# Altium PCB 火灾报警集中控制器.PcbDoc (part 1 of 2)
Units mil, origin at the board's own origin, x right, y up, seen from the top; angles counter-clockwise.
Board outline 3890 x 3920 mil, 2 copper layers (Top Layer, Bottom Layer); 74 components, 132 nets, 502 pads, 181 vias.
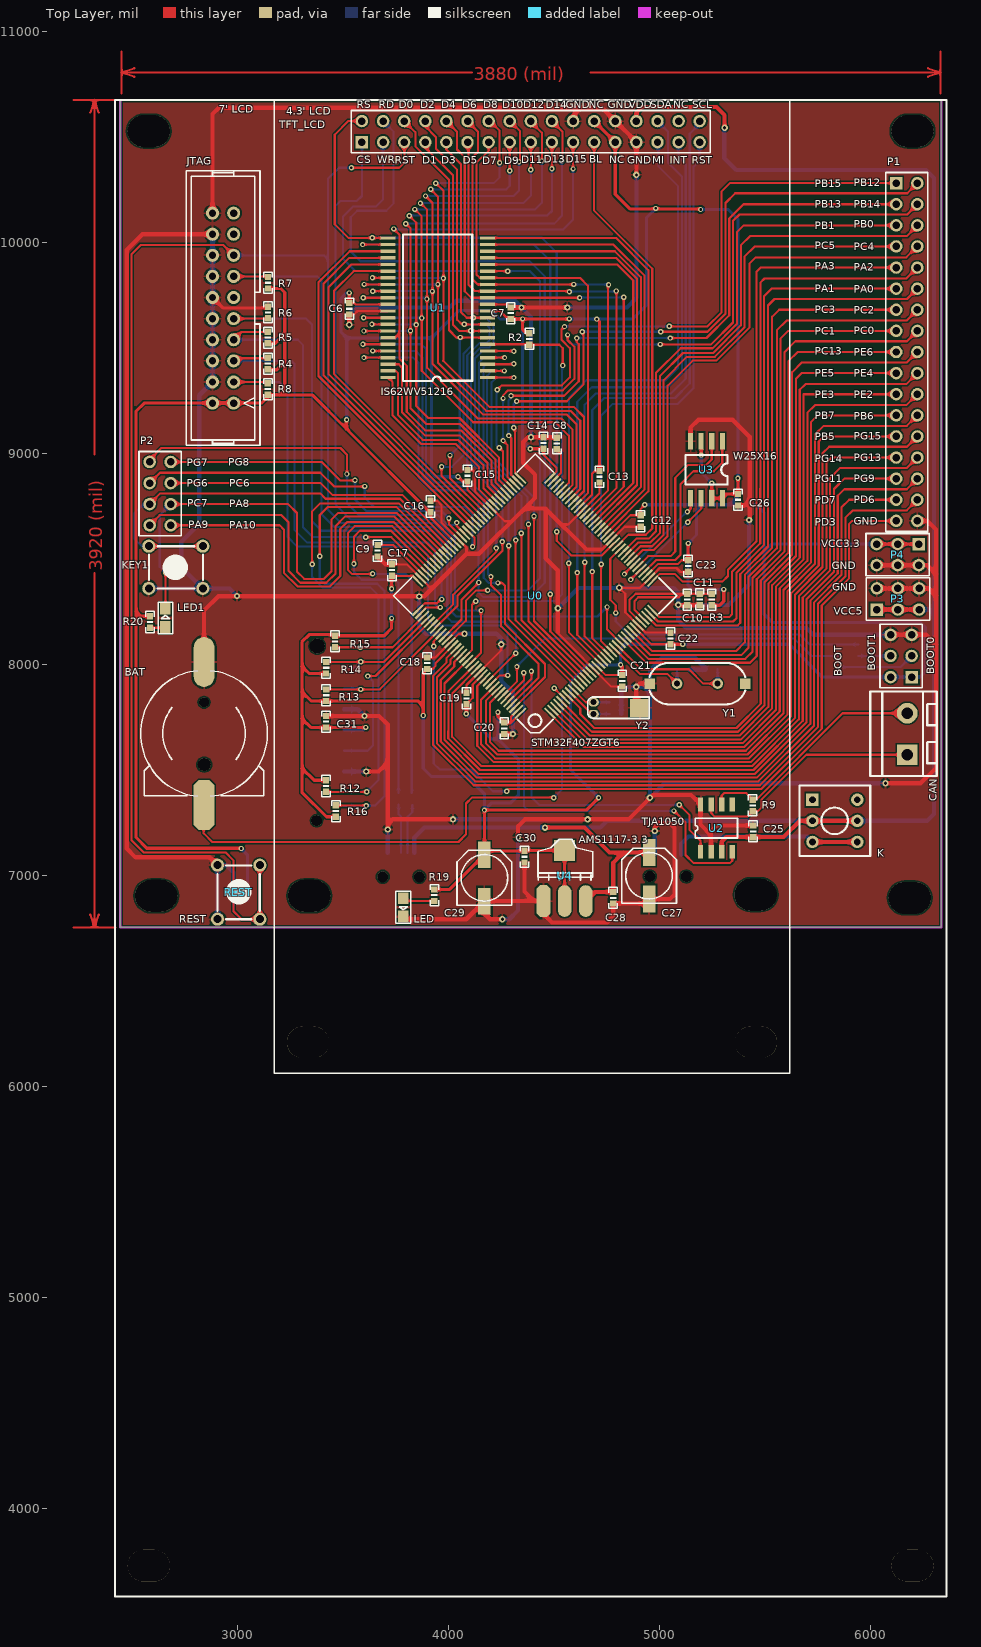
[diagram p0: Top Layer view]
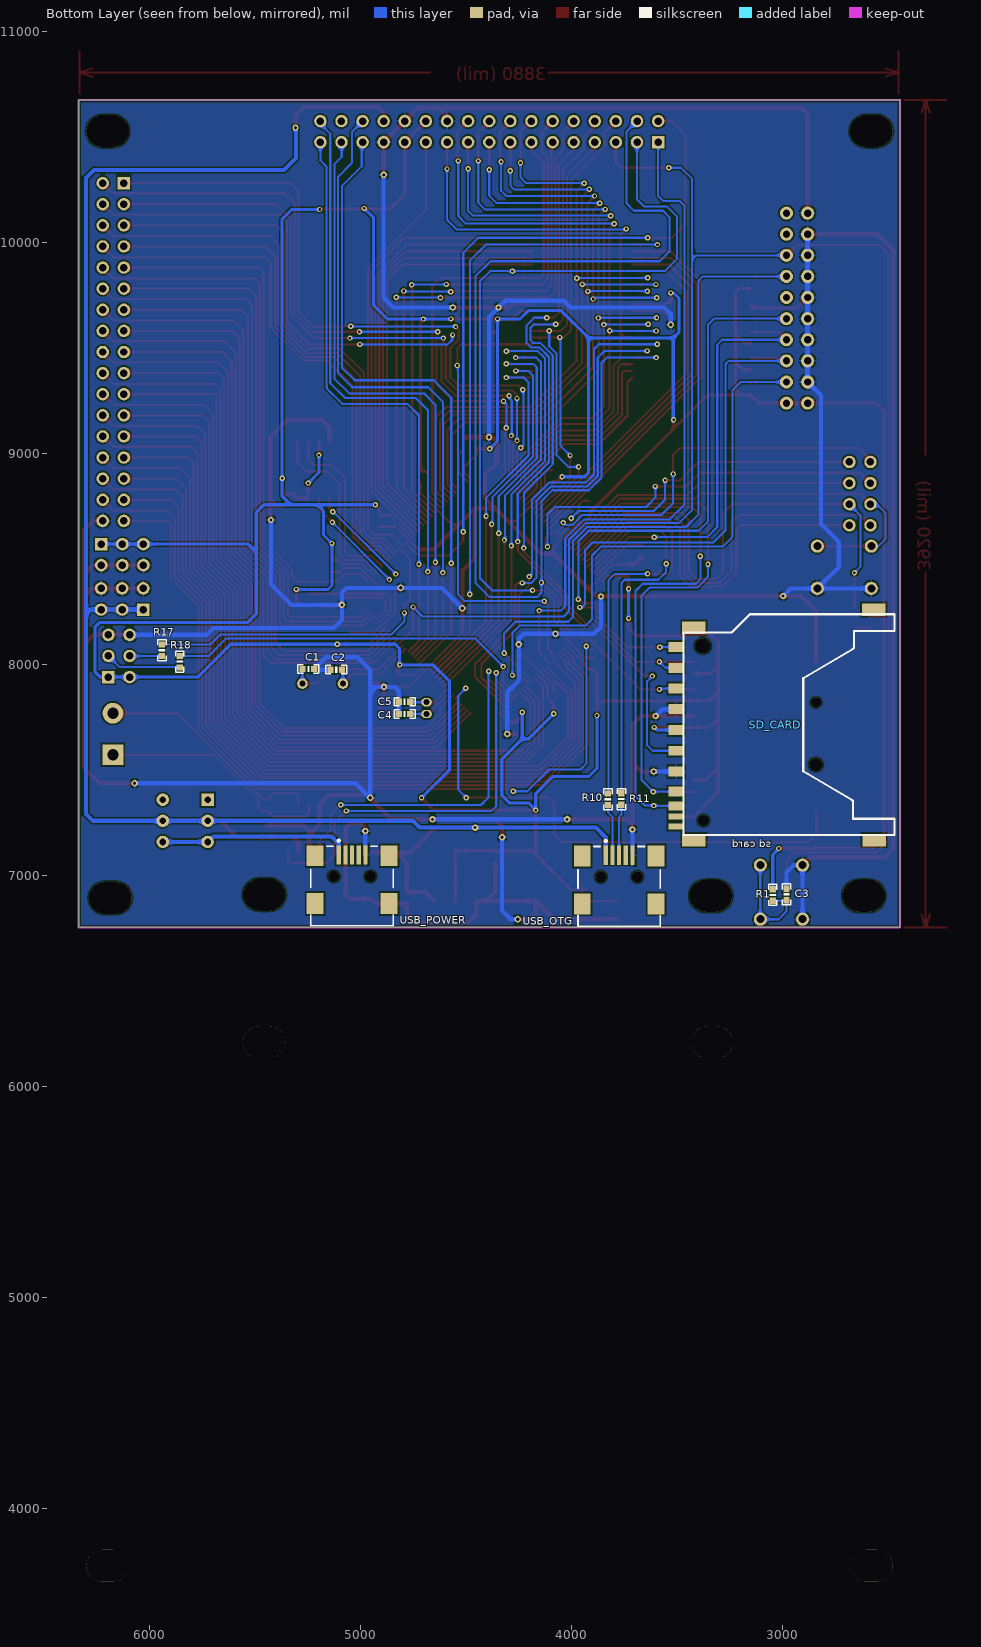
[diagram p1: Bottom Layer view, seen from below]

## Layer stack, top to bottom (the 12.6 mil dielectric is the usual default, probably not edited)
Top Solder: solder mask 0.4, Solder Resist, Dk 3.5
Top Layer: signal copper 1.4
Dielectric 1: dielectric 12.6, FR-4, Dk 4.8
Bottom Layer: signal copper 1.4
Bottom Solder: solder mask 0.4, Solder Resist, Dk 3.5

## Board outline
2445,6755 6335,6755 6335,10675 2445,10675

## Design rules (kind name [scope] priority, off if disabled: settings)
Clearance [All] p1: gap=8
PolygonConnect [All] p1: connectstyle=Relief reliefconductorwidth=10 reliefentries=4 polygonreliefangle="90 Angle" airgapwidth=10
RoutingVias [All] p1: holewidth=28 width=50 viastyle="Through Hole" minholewidth=28 minwidth=50 maxholewidth=28 maxwidth=50
SilkToBoardRegionClearance [InNetClass('All Nets')] p1:
SolderMaskExpansion [All] p1: expansion=4
Width VCC3.3_10mil [InNet('VCC3.3')] p1 off: maxlimit=10 minlimit=10 preferedwidth=10
Width GND_10mil [InNet('GND')] p2 off: maxlimit=10 minlimit=10 preferedwidth=10
Width USB_VCC [InNet('USB_VCC')] p3: maxlimit=20 minlimit=20 preferedwidth=20
Width GND_20mil [InNet('GND')] p4: maxlimit=20 minlimit=20 preferedwidth=20
Width VCC5 [InNet('VCC5')] p5: maxlimit=20 minlimit=20 preferedwidth=20
Width VCC3.3_mil [InNet('VCC3.3')] p6: maxlimit=15 minlimit=15 preferedwidth=15
Width [All] p7: maxlimit=10 minlimit=10 preferedwidth=10
28 further rules are at their usual default settings.

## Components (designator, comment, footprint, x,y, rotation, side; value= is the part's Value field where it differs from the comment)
BAT "BATT" BATM 2842,7674 r0 top (schematic designator BAT1)
BOOT "Header 3X2" HDR2X3 6194,7941 r90 top
C1 "22" 0603P 5247,7979 r0 bottom
C2 "22" 0603P 5115,7976 r180 bottom
C3 "104" 0603P 2982,6912 r270 bottom
C4 "10" 0603P 4791,7766 r0 bottom
C5 "10" 0603P 4791,7824 r0 bottom
C6 "104" 0603P 3530,9686 r90 top
C7 "104" 0603P 4295,9665 r270 top
C8 "225" 0603P 4513,9048 r90 top
C9 "225" 0603P 3664,8540 r270 top
C10 "10uF" 0603P 5131,8308 r90 top
C11 "104" 0603P 5190,8309 r90 top
C12 "104" 0603P 4910,8680 r90 top
C13 "104" 0603P 4715,8890 r90 top
C14 "104" 0603P 4450,9050 r270 top
C15 "104" 0603P 4090,8895 r270 top
C16 "104" 0603P 3915,8749 r270 top
C17 "104" 0603P 3732,8448 r270 top
C18 "104" 0603P 3899,8007 r270 top
C19 "104" 0603P 4085,7840 r270 top
C20 "104" 0603P 4264,7698 r90 top
C21 "104" 0603P 4823,7923 r90 top
C22 "104" 0603P 5052,8124 r270 top
C23 "104" 0603P 5135,8467 r90 top
C25 "104" 0603P 5443,7210 r90 top
C26 "104" 0603P 5371,8781 r90 top
C27 "220uF" CC6.56.5 4950,7000 r270 top
C28 "104" 0603P 4780,6895 r90 top
C29 "220uF" CC6.56.5 4170,6990 r270 top
C30 "104" 0603P 4360,7090 r90 top
C31 "104" 0603P 3420,7730 r270 top
CAN "CAN" HEAD2L-0.8 6173,7573 r90 top (schematic designator CAN1)
JTAG "JTAG" JTAG_20 2932,9689 r90 top (schematic designator JTAG1)
K "BUTTON" BTN8.5*8.5 5724,7360 r0 top (schematic designator K2)
KEY1 "KEY_M" KEY_M 2836,8361 r180 top
LED "LED" SMDLED 3786,6894 r270 top (schematic designator LED1)
LED1 "LED" SMDLED 2659,8178 r90 top (schematic designator LED2)
P1 "Header2x17" Header2x17 6121,10281 r0 top
P2 "Header2x4" Header2x4 2584,8960 r0 top
P3 "VCC5" HDR2X3 6029,8261 r0 top
P4 "VCC3.3" HDR2X3 6228,8571 r180 top
R1 "10K" 0603P 3047,6909 r270 bottom
R2 "10K" 0603P 4383,9543 r270 top
R3 "10R" 0603P 5247,8308 r270 top
R4 "10K" 0603P 3144,9426 r90 top
R5 "10K" 0603P 3144,9549 r90 top
R6 "10K" 0603P 3145,9669 r270 top
R7 "10K" 0603P 3145,9809 r90 top
R8 "10K" 0603P 3144,9305 r90 top
R9 "120R" 0603P 5441,7333 r90 top
R10 "22R" 0603P 3828,7362 r90 bottom
R11 "22R" 0603P 3764,7363 r90 bottom
R12 "47K" 0603P 3420,7425 r270 top
R13 "47K" 0603P 3420,7855 r90 top
R14 "47K" 0603P 3420,7985 r90 top
R15 "47K" 0603P 3462,8110 r270 top
R16 "47K" 0603P 3466,7306 r90 top
R17 "10K" 0603P 5941,8068 r90 bottom
R18 "10K" 0603P 5856,8014 r270 bottom
R19 "200R" 0603P 3933,6908 r270 top
R20 "200R" 0603P 2586,8202 r270 top
REST "REST" KEY_M 2906,6794 r90 top
SD_CARD "sd card" SDCARD_L 3505,7985 r90 bottom
TFT_LCD "ATK 7‘ TFT LCD" "7’ TFT LCD" 3590,10475 r0 top locked (schematic designator TFT_LCD1)
U0 "STM32F407ZGT6" LQFP144 4480,7770 r135 top
U1 "IS62WV51216" TSOP44 4185,9360 r180 top
U2 "TJA1050" SOP-8 5194,7113 r90 top
U3 "W25X16" SOIC-8 5297,9058 r270 top
U4 "AMS1117-3.3" AMS1117 4450,6880 r0 top
USB_OTG "USB-B(Mini)" USB/SM0.8-6H5 3775,6788 r270 bottom
USB_POWER "USB-B(Mini)" USB/SM0.8-6H5 5040,6790 r270 bottom
Y1 "8MHz" XTAL_US 5275,7910 r180 top
Y2 "32.768K" XTAL32 4687,7822 r0 top

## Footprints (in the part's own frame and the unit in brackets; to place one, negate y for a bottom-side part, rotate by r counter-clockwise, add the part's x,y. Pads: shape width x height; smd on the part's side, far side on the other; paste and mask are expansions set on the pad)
"7’ TFT LCD" [mm]
  rect 1.5x1.5 hole 0.9: 1(0,0)
  round 1.5 hole 0.9: 2(0,2.54) 3(2.54,0) 4(2.54,2.54) 5(5.08,0) 6(5.08,2.54) 7(7.62,0) 8(7.62,2.54) 9(10.16,0) 10(10.16,2.54) 11(12.7,0) 12(12.7,2.54) 13(15.24,0) 14(15.24,2.54) 15(17.78,0) 16(17.78,2.54) 17(20.32,0) 18(20.32,2.54) 19(22.86,0) 20(22.86,2.54) 21(25.4,0) 22(25.4,2.54) 23(27.94,0) 24(27.94,2.54) 25(30.48,0) 26(30.48,2.54) 27(33.02,0) 28(33.02,2.54) 29(35.56,0) 30(35.56,2.54) 31(38.1,0) 32(38.1,2.54) 33(40.64,0) 34(40.64,2.54)
  oval 5.08x3.81 hole 3.81 slot 5.08 at 0 deg unplated: ""(-25.654,-171.272) ""(-25.654,1.321) ""(-6.477,-108.306) ""(47.396,-108.306) ""(66.243,-171.272) ""(66.243,1.321)
  silkscreen extent -29.72,-175.01 70.36,5.08
0603P [mil]
  rect 30x30 smd: 1(-27,0) 2(27.5,-0.06)
  silkscreen extent -50,-20 50,20
AMS1117 [mil]
  oct 65x150 smd: 1(0.03,-0.06)
  oval 65x150 smd: 2(100.03,-0.06) 3(200.03,-0.06)
  rect 100x100 smd: 4(100.03,239.94)
  silkscreen extent -26,100 234,293
BATM [mil]
  oct 98.43x236.22 smd: 1(0,-338.65)
  oval 98.43x236.22 smd: 2(0,338.52)
  round 45 hole 45 slot 46 at 0 deg unplated paste+0 mask+0: ""(0,147.57)
  round 60 hole 60 slot 61 at 0 deg unplated paste+0 mask+0: ""(0.98,-147.7)
  silkscreen extent -300,-298 300,298
BTN8.5*8.5 [mm]
  rect 1.5x1.5 hole 0.8: 1(0,0)
  round 1.5 hole 0.8: 2(0,-2.54) 3(0,-5.08) 4(5.4,-5.08) 5(5.4,-2.54) 6(5.4,0)
  silkscreen extent -1.55,-6.79 6.95,1.71
CC6.56.5 [mm]
  rect 3.2x1.5 smd: 1(-2.794,0) 2(2.8,0)
  silkscreen extent -3.3,-3.3 3.3,3.3
HDR2X3 [mm]
  rect 1.5x1.5 hole 0.9: 1(0,0)
  round 1.5 hole 0.9: 2(0,2.54) 3(2.54,0) 4(2.54,2.54) 5(5.08,0) 6(5.08,2.54)
  silkscreen extent -1.27,-1.27 6.35,3.81
HEAD2L-0.8 [mm]
  rect 2.5x2.5 hole 1.35: 1(0,0)
  round 2.5 hole 1.35: 2(5,0)
  silkscreen extent -2.54,-3.56 7.62,4.45
Header2x4 [mm]
  round 1.5 hole 0.9: 1(0,0) 2(2.54,0) 3(0,-2.54) 4(2.54,-2.54) 5(0,-5.08) 6(2.54,-5.08) 7(0,-7.62) 8(2.54,-7.62)
  silkscreen extent -1.27,-8.89 3.81,1.27
Header2x17 [mm]
  rect 1.5x1.5 hole 0.9: 1(0,0)
  round 1.5 hole 0.9: 2(2.54,0) 3(0,-2.54) 4(2.54,-2.54) 5(0,-5.08) 6(2.54,-5.08) 7(0,-7.62) 8(2.54,-7.62) 9(0,-10.16) 10(2.54,-10.16) 11(0,-12.7) 12(2.54,-12.7) 13(0,-15.24) 14(2.54,-15.24) 15(0,-17.78) 16(2.54,-17.78) 17(0,-20.32) 18(2.54,-20.32) 19(0,-22.86) 20(2.54,-22.86) 21(0,-25.4) 22(2.54,-25.4) 23(0,-27.94) 24(2.54,-27.94) 25(0,-30.48) 26(2.54,-30.48) 27(0,-33.02) 28(2.54,-33.02) 29(0,-35.56) 30(2.54,-35.56) 31(0,-38.1) 32(2.54,-38.1) 33(0,-40.64) 34(2.54,-40.64)
  silkscreen extent -1.27,-41.91 3.81,1.27
JTAG_20 [mil]
  round 62 hole 35: 1(-450,-50) 2(-450,50) 3(-350,-50) 4(-350,50) 5(-250,-50) 6(-250,50) 7(-150,-50) 8(-150,50) 9(-50,-50) 10(-50,50) 11(50,-50) 12(50,50) 13(150,-50) 14(150,50) 15(250,-50) 16(250,50) 17(350,-50) 18(350,50) 19(450,-50) 20(450,50)
  silkscreen extent -650,-175 650,175
KEY_M [mil]
  round 62 hole 38: 1(0,0) 1(255.91,0) 2(0,-200) 2(255.91,-200)
  silkscreen extent 0,-200 255,0
LQFP144 [mil]
  rect 70.87x10 smd: 1(-0.36,0.02) 2(-0.35,-19.66) 3(-0.35,-39.35) 4(-0.35,-59.03) 5(-0.35,-78.72) 6(-0.35,-98.4) 7(-0.35,-118.09) 8(-0.35,-137.77) 9(-0.35,-157.46) 10(-0.35,-177.14) 11(-0.35,-196.83) 12(-0.36,-216.51) 13(-0.35,-236.2) 14(-0.35,-255.88) 15(-0.35,-275.57) 16(-0.35,-295.25) 17(-0.35,-314.94) 18(-0.35,-334.62) 19(-0.35,-354.31) 20(-0.35,-373.99) 21(-0.36,-393.68) 22(-0.35,-413.36) 23(-0.35,-433.05) 24(-0.35,-452.73) 25(-0.35,-472.42) 26(-0.35,-492.1) 27(-0.35,-511.79) 28(-0.35,-531.47) 29(-0.35,-551.16) 30(-0.35,-570.84) 31(-0.35,-590.53) 32(-0.36,-610.21) 33(-0.35,-629.9) 34(-0.35,-649.58) 35(-0.35,-669.27) 36(-0.35,-688.95) 73(885.47,-688.95) 74(885.47,-669.27) 75(885.47,-649.58) 76(885.47,-629.9) 77(885.47,-610.21) 78(885.47,-590.53) 79(885.47,-570.84) 80(885.47,-551.16) 81(885.47,-531.47) 82(885.47,-511.79) 83(885.47,-492.1) 84(885.47,-472.42) 85(885.47,-452.73) 86(885.47,-433.05) 87(885.47,-413.36) 88(885.47,-393.68) 89(885.47,-373.99) 90(885.47,-354.31) 91(885.47,-334.62) 92(885.47,-314.94) 93(885.47,-295.25) 94(885.47,-275.57) 95(885.47,-255.88) 96(885.47,-236.2) 97(885.47,-216.51) 98(885.47,-196.83) 99(885.47,-177.14) 100(885.47,-157.46) 101(885.47,-137.77) 102(885.47,-118.09) 103(885.47,-98.4) 104(885.47,-78.72) 105(885.47,-59.03) 106(885.47,-39.35) 107(885.47,-19.66) 108(885.47,0.02)
  rect 10x70.87 smd: 37(98.07,-787.37) 38(117.76,-787.38) 39(137.44,-787.38) 40(157.13,-787.38) 41(176.81,-787.38) 42(196.5,-787.38) 43(216.18,-787.38) 44(235.87,-787.38) 45(255.55,-787.38) 46(275.24,-787.38) 47(294.92,-787.38) 48(314.61,-787.37) 49(334.29,-787.38) 50(353.98,-787.38) 51(373.66,-787.38) 52(393.35,-787.38) 53(413.03,-787.38) 54(432.72,-787.38) 55(452.4,-787.38) 56(472.09,-787.38) 57(491.77,-787.38) 58(511.46,-787.37) 59(531.14,-787.38) 60(550.83,-787.38) 61(570.51,-787.38) 62(590.2,-787.38) 63(609.88,-787.38) 64(629.57,-787.38) 65(649.25,-787.38) 66(668.94,-787.38) 67(688.62,-787.38) 68(708.31,-787.37) 69(727.99,-787.38) 70(747.68,-787.38) 71(767.36,-787.38) 72(787.05,-787.38) 109(787.05,98.45) 110(767.36,98.45) 111(747.68,98.45) 112(727.99,98.45) 113(708.31,98.45) 114(688.62,98.45) 115(668.94,98.45) 116(649.25,98.45) 117(629.57,98.45) 118(609.88,98.45) 119(590.2,98.45) 120(570.51,98.45) 121(550.83,98.45) 122(531.14,98.45) 123(511.46,98.45) 124(491.77,98.45) 125(472.09,98.45) 126(452.4,98.45) 127(432.72,98.45) 128(413.03,98.45) 129(393.35,98.45) 130(373.66,98.45) 131(353.98,98.45) 132(334.29,98.45) 133(314.61,98.45) 134(294.92,98.45) 135(275.24,98.45) 136(255.55,98.45) 137(235.87,98.45) 138(216.18,98.45) 139(196.5,98.45) 140(176.81,98.45) 141(157.13,98.45) 142(137.44,98.45) 143(117.76,98.45) 144(98.07,98.45)
  silkscreen extent -32,-819 917,130
SDCARD_L [mm]
  rect 1.2x1.8 smd: 1(0,0) 2(-2.489,0) 3(-4.983,-0.009) 4(-7.483,-0.009) 5(-9.983,-0.009) 6(-12.483,-0.009) 7(-14.908,-0.009) 9(2.517,-0.009)
  rect 1.1x1.8 smd: 8(-16.612,0)
  rect 0.7x1.8 smd: 10(-17.908,-0.009) 12(-19.101,0)
  rect 1.5x2.8 smd: 11(-20.726,-23.834) 11(-20.726,-2.143) 11(4.826,-2.143) 11(7.01,-23.784)
  silkscreen extent -20.13,-26.3 6.44,-0.9
SMDLED [mm]
  rect 1.4x1.27 smd: 1(0.001,-0.002) 2(2.211,-0.002)
  silkscreen extent -0.8,-0.89 3.01,0.89
SOIC-8 [mil]
  rect 80x24 smd: 1(0,0) 2(0,-50.06) 3(0,-100.06) 4(0,-150.06) 5(270,-150) 6(270,-100) 7(270,-50) 8(270,0)
  silkscreen extent 65,-175 205,25
SOP-8 [mil]
  rect 65x25 smd: 1(0,0) 2(0,-50) 3(0,-100) 4(0,-150) 5(224.41,-150) 6(224.41,-100) 7(224.41,-50) 8(224.41,0)
  silkscreen extent 65,-175 159,25
TSOP44 [mm]
  rect 1.8x0.4 smd: 1(-0.009,0.001) 2(-0.009,-0.799) 3(-0.009,-1.599) 4(-0.009,-2.399) 5(-0.009,-3.199) 6(-0.009,-3.999) 7(-0.009,-4.799) 8(-0.009,-5.599) 9(-0.009,-6.399) 10(-0.009,-7.199) 11(-0.009,-7.999) 12(-0.009,-8.799) 13(-0.009,-9.599) 14(-0.009,-10.399) 15(-0.009,-11.199) 16(-0.009,-11.999) 17(-0.009,-12.799) 18(-0.009,-13.599) 19(-0.009,-14.399) 20(-0.009,-15.199) 21(-0.009,-15.999) 22(-0.009,-16.799) 23(11.991,-16.799) 24(11.991,-15.999) 25(11.991,-15.199) 26(11.991,-14.399) 27(11.991,-13.599) 28(11.991,-12.799) 29(11.991,-11.999) 30(11.991,-11.199) 31(11.991,-10.399) 32(11.991,-9.599) 33(11.991,-8.799) 34(11.991,-7.999) 35(11.991,-7.199) 36(11.991,-6.399) 37(11.991,-5.599) 38(11.991,-4.799) 39(11.991,-3.999) 40(11.991,-3.199) 41(11.991,-2.399) 42(11.991,-1.599) 43(11.991,-0.799) 44(11.991,0.001)
  silkscreen extent 1.83,-17.2 10.16,0.4
USB/SM0.8-6H5 [mm]
  rect 2.3x0.5 smd: 1(-7.85,-1.6) 2(-7.85,-0.8) 3(-7.85,0) 4(-7.85,0.8) 5(-7.85,1.6)
  rect 2.5x2 smd: 6(-7.75,4.45) 7(-1.996,4.45) 8(-7.75,-4.45) 9(-1.996,-4.45)
  round 1.27 hole 1.27 slot 1.295 at 0 deg unplated: MH1(-5.25,2.2) MH2(-5.25,-2.2)
  silkscreen extent -9.67,-4.95 0.7,4.95
XTAL32 [mil]
  oval 50x40 hole 28: 1(0,0) 2(0,-56)
  rect 92.13x86 smd: ""(220,-27)
  silkscreen extent -28,-77 264,25
XTAL_US [mil]
  round 50 hole 28: 1(0,0) 2(192.13,0)
  rect 50x50 smd: ""(-130.32,0) ""(322.44,0)
  silkscreen extent -131,-98 323,98

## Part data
BAT: library part BAT
BOOT: "Header, 3-Pin, Dual row"
C1 C2 C3 C4 C5 C6 C7 C8 C9 C10 C11 C12 C13 C14 C15 C16 C17 C18 C19 C20 C21 C22 C23 C25 C26 C28 C30 C31: library part C
C27 C29: library part CAP
CAN: library part HEAD2
LED LED1: library part LED2, "Typical RED, GREEN, YELLOW, AMBER GaAs LED"
P3 P4: library part "Header 3X2", "Header, 3-Pin, Dual row"
R1 R2 R3 R4 R5 R6 R7 R8 R9 R10 R11 R12 R13 R14 R15 R16 R17 R18 R19 R20: library part R
REST: library part KEY
U0: library part STM32F407ZET6, "STM32F407ZET6"
U2: library part SN65HVD230D
U3: "W25X16;SST25VF016;MX25L1605"
U4: library part AMS1117
USB_OTG USB_POWER: library part USB5
Y1 Y2: library part XTAL, "Crystal Oscillator"

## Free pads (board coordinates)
  oval 200x150 hole 150 slot 200 at 0 deg unplated paste+0: ""(2615,6905) ""(3340,6905) ""(5455,6910)
  round 50 hole 50 slot 51 at 0 deg unplated paste+0 mask+0: ""(3375,7261)
  round 70 hole 70 slot 71 at 0 deg unplated paste+0 mask+0: ""(3378,8088)
  oval 200x150 hole 150 slot 200 at 0 deg unplated: ""(6185,6895)

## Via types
v1: diameter 25, hole 12, Top Layer to Bottom Layer, 154 vias
v2: diameter 30, hole 15, Top Layer to Bottom Layer, 27 vias

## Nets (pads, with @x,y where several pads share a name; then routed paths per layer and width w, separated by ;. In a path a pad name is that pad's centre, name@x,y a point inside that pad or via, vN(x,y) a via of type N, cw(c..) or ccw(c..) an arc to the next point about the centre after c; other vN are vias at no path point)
BOOT0: R18.1 U0.138 | length 1787.2
  Top Layer w10: U0.138@4257.52,7853.25 4324,7919.73 v1(4324,7991)
  Bottom Layer w10: v1(4324,7991) 4457.5,8124.5 5636,8124.5 5719.5,8041 R18.1@5856,8041
BOOT1: R17.2 U0.48 | length 1569.9
  Top Layer w10: v1(4792,8245) 4792,8281 4766,8307 4766,8500.92 U0.48@4814.3,8549.22
  Bottom Layer w10: v1(4792,8245) 4792,8204 4853.5,8142.5 5664,8142.5 5711,8095.5 R17.2@5940.94,8095.5
CAN_RX: U0.139 U2.4 | length 2025.5
  Top Layer w10: U0.139@4271.44,7839.33 4357,7924.89 v1(4357,7962) ; v1(5068,7307) 5123,7252 5123,7098 5160,7061 5334,7061 5344,7071 U2.4@5344,7113
  Bottom Layer w10: v1(4357,7962) 4357,7329 4379,7307 v1(5068,7307)
CAN_TX: U0.140 U2.1 | length 1763.4
  Top Layer w10: U0.140@4285.36,7825.41 4393,7933.05 v1(4393,7969) ; v1(5093,7336) 5141,7288 5141,7218 5194,7165 U2.1@5194,7113
  Bottom Layer w10: v1(4393,7969) 4393,7371 4429,7335 v1@5090.46,7335
FSMC_A0: U0.10 U1.5 | length 2082.6
  Top Layer w10: U1.5@4185.35,9485.96 4309.04,9485.96 v1(4310,9485) ; v1(4285,8563) 4285,8215.52 U0.10@4605.51,7895.01
  Bottom Layer w10: v1@4285,8559 4285,8806.63 4125,8966.63 4125,9450 4160,9485 v1(4310,9485)
FSMC_A1: U0.11 U1.4 | length 1933.4
  Top Layer w10: U1.4@4185.35,9454.46 v1(4265.54,9454.46) ; v1(4318,8590) 4318,8210.35 U0.11@4619.43,7908.93
  Bottom Layer w10: v1(4265.54,9454.46) 4167.46,9454.46 4145,9432 4145,8972.09 4315,8802.09 v1@4315,8585
FSMC_A2: U0.12 U1.3 | length 1960.7
  Top Layer w10: U1.3@4185.35,9422.97 4307.97,9422.97 v1(4310,9425) ; v1(4345,8623) 4345,8211.19 U0.12@4633.35,7922.85
  Bottom Layer w10: v1(4310,9425) 4182,9425 4165,9408 4165,8977.54 4345,8797.54 v1@4345,8619
FSMC_A3: U0.13 U1.2 | length 1796.8
  Top Layer w10: U1.2@4185.35,9391.47 v1(4265,9391.47) ; v1(4379,8665) 4379,8205.03 U0.13@4647.27,7936.77
  Bottom Layer w10: v1(4265,9391.47) 4205.47,9391.47 4183,9369 4183,8985 4375,8793 v1@4375,8662
FSMC_A4: U0.14 U1.1 | length 1816.4
  Top Layer w10: U1.1@4185.35,9359.98 v1(4310,9359.98) ; v1(4405,8703) 4405,8206.87 U0.14@4661.19,7950.69
  Bottom Layer w10: v1(4310,9359.98) 4225.98,9359.98 4204,9338 4204,8991 4405,8790 v1(4405,8703)
FSMC_A5: U0.15 U1.24 | length 3069.1
  Top Layer w10: v1(3593,9989.9) U1.24@3712.91,9989.9 ; v1(4482,8333) 4482,8157.71 U0.15@4675.1,7964.6
  Bottom Layer w10: v1(3593,9989.9) 4405.1,9989.9 4482,9913 v1(4482,8333)
FSMC_A6: TFT_LCD.2 U0.50 U1.23 | length 3454.5
  Top Layer w10: TFT_LCD.2@3590,10575 3525,10575 3461,10511 3461,10086 3525.61,10021.39 U1.23@3712.91,10021.39 ; v1(4513,8629) 4513,8586 4582,8517 4726.4,8517 U0.50@4786.46,8577.06
  Bottom Layer w10: v1(3639,10022) 4442,10022 4513,9951 v1(4513,8629)
FSMC_A7: U0.53 U1.22 | length 2158.2
  Top Layer w10: U1.22@4185.35,10021.39 4793.61,10021.39 4947,9868 4947,8821.11 U0.53@4744.7,8618.82
FSMC_A8: U0.54 U1.21 | length 2096.5
  Top Layer w10: U1.21@4185.35,9989.9 4781.47,9989.9 4929,9842.37 4929,8830.95 U0.54@4730.78,8632.74
FSMC_A9: U0.55 U1.20 | length 2045.5
  Top Layer w10: U1.20@4185.35,9958.4 4787.51,9958.4 4911,9834.91 4911,8840.79 U0.55@4716.86,8646.65
FSMC_A10: U0.56 U1.19 | length 1994.4
  Top Layer w10: U1.19@4185.35,9926.91 4793.55,9926.91 4893,9827.46 4893,8850.63 U0.56@4702.94,8660.57
FSMC_A11: U0.57 U1.18 | length 1943.4
  Top Layer w10: U1.18@4185.35,9895.41 4799.59,9895.41 4875,9820 4875,8860.47 U0.57@4689.03,8674.49
FSMC_A12: U0.87 U1.28 | length 1661.8
  Top Layer w10: U1.28@3712.91,9863.91 3551.09,9863.91 3457,9769.83 3457,9377.58 U0.87@4146.17,8688.41
FSMC_A13: U0.88 U1.27 | length 1729.5
  Top Layer w10: U1.27@3712.91,9895.41 3538.41,9895.41 3432,9789 3432,9374.74 U0.88@4132.25,8674.49
FSMC_A14: U0.89 U1.26 | length 1794.1
  Top Layer w10: U1.26@3712.91,9926.91 3529.91,9926.91 3408,9805 3408,9370.91 U0.89@4118.33,8660.58
FSMC_A15: U0.90 U1.25 | length 1852.7
  Top Layer w10: U1.25@3712.91,9958.4 3531.4,9958.4 3384,9811 3384,9367.06 U0.90@4104.41,8646.66
FSMC_A16: U0.80 U1.42 | length 983.8
  Top Layer w10: U1.42@3712.91,9422.97 3764.03,9422.97 3779.35,9407.65 3779.35,9195.2 3889.54,9085 4055,9085 4185,8955 4185,8844.45 U0.80@4243.6,8785.85
FSMC_A17: U0.81 U1.43 | length 952.9
  Top Layer w10: U1.43@3712.91,9391.47 3749.53,9391.47 3761.35,9379.65 3761.35,9181.65 3878,9065 4045,9065 4165,8945 4165,8836.61 U0.81@4229.68,8771.93
FSMC_A18: U0.82 U1.44 | length 906.9
  Top Layer w10: U1.44@3712.91,9359.98 3735,9337.89 3735,9180 3870,9045 4035,9045 4145,8935 4145,8828.77 U0.82@4215.76,8758.01
FSMC_D0: TFT_LCD.6 U0.85 U1.7 | length 2199.3
  Top Layer w10: TFT_LCD.6@3790,10575 3843,10522 3843,10456 4002,10297 4002,9585 4038.05,9548.95 U1.7@4185.35,9548.95 ; v1(4007,8991) 4007,8883.26 U0.85@4174.01,8716.25
  Bottom Layer w10: v1(4007,8991) 4053,9037 4053,9547 v1(4056,9550)
FSMC_D1: TFT_LCD.7 U0.86 U1.8 | length 2140.8
  Top Layer w10: TFT_LCD.7@3890,10475 3890,10449 4021,10318 4021,9610 4050.55,9580.45 U1.8@4185.35,9580.45 ; v1(3967,8937) 3967,8895.42 U0.86@4160.09,8702.33
  Bottom Layer w10: v1(3967,8937) 4016,8937 4071,8992 4071,9472.37 4106,9507.37 v1(4106,9581)
FSMC_D2: TFT_LCD.8 U0.114 U1.9 | length 2936.2
  Top Layer w10: TFT_LCD.8@3890,10575 3890,10550.07 3941,10499.07 3941,10444 4041,10344 4041,9634 4063.05,9611.95 v1(4075,9611.95) U1.9@4185.35,9611.95 ; U0.114@3923.46,8187.31 4022,8285.86 4022,8331 4226,8535 v1(4226,8552)
  Bottom Layer w10: v1(4075,9611.95) 4178.05,9611.95 4194,9596 4194,9537 4181.46,9524.46 4148.54,9524.46 4089,9464.91 4089,8950 4226,8813 v1(4226,8552)
FSMC_D3: TFT_LCD.9 U0.115 U1.10 | length 2776.9
  Top Layer w10: U0.115@3937.38,8173.4 4042,8278.02 4042,8325 4255,8538 v1(4255,8583) ; TFT_LCD.9@3990,10475 3990,10440 4059,10371 4059,9670 4085.56,9643.44 v1(4117,9643.44) U1.10@4185.35,9643.44
  Bottom Layer w10: v1(4117,9643.44) 4176.56,9643.44 4214,9606 4214,9524 4193,9503 4152.54,9503 4107,9457.46 4107,8959.18 4255,8811.18 v1(4255,8583)
FSMC_D4: TFT_LCD.10 U0.58 U1.13 | length 2724.2
  Top Layer w10: TFT_LCD.10@3990,10575 4040,10525 4040,10440 4077,10403 4077,9768 4107.07,9737.93 U1.13@4185.35,9737.93 v1(4621,9737.93) ; U0.58@4675.1,8688.41 4830,8843.31 v1(4830,9740)
  Bottom Layer w10: v1@4621,9740 v1(4830,9740)
FSMC_D5: TFT_LCD.11 U0.59 U1.14 | length 2515.1
  Top Layer w10: TFT_LCD.11@4090,10475 4095,10470 4095,9800 4125.57,9769.43 U1.14@4185.35,9769.43 4570.57,9769.43 v1(4573,9767) ; U0.59@4661.19,8702.33 4795,8836.15 v1(4795,9770)
  Bottom Layer w10: v1(4573,9767) 4792,9767 v1(4795,9770)
FSMC_D6: TFT_LCD.12 U0.60 U1.15 | length 2565.7
  Top Layer w10: TFT_LCD.12@4090,10575 4140,10525 4140,10430 4113,10403 4113,9827 4139.08,9800.92 U1.15@4185.35,9800.92 v1(4593,9800.92) ; U0.60@4647.27,8716.25 4755,8823.99 4755,9797 v1(4758,9800)
  Bottom Layer w10: v1(4593,9800.92) 4757.08,9800.92 v1(4758,9800)
FSMC_D7: TFT_LCD.13 U0.63 U1.16 | length 2260.5
  Top Layer w10: TFT_LCD.13@4190,10475 4190,10435 4132,10377 4132,9848 4147.58,9832.42 U1.16@4185.35,9832.42 4622.58,9832.42 4660,9795 4660,8812.5 U0.63@4605.51,8758.01
FSMC_D8: TFT_LCD.14 U0.64 U1.29 | length 3056.7
  Top Layer w10: v1(3639.58,9832.42) U1.29@3712.91,9832.42 ; v1(3940,10281) 3976,10245 v1(3976,9831) 3976,9439.54 ; 3975,9439.54 4194.54,9220 4595,9220 4642,9173 4642,8822.34 U0.64@4591.59,8771.93 ; TFT_LCD.14@4190,10575 4196,10575 4242,10529 v1(4242,10378)
  Bottom Layer w10: v1(3639.58,9832.42) v1@3974.58,9832.42 ; v1@3952,10281 4214,10281 4242,10309 v1(4242,10378)
FSMC_D9: TFT_LCD.15 U0.65 U1.30 | length 3058.1
  Top Layer w10: v1(3600.08,9800.92) U1.30@3712.91,9800.92 ; v1(3915.5,10251.5) 3950,10217 v1(3950,9801) 3950,9430 4178,9202 4578,9202 4624,9156 4624,8832.18 U0.65@4577.67,8785.85 ; v1(4290,10340) TFT_LCD.15@4290,10475
  Bottom Layer w10: v1(3600.08,9800.92) v1@3949.92,9800.92 ; v1@3921,10251.5 4273.5,10251.5 4290,10268 v1(4290,10340)
FSMC_D10: TFT_LCD.16 U0.66 U1.31 | length 3125.9
  Top Layer w10: v1(3640.57,9769.43) U1.31@3712.91,9769.43 ; v1(3891,10220) 3924,10187 v1(3924,9768) 3924,9425 4165,9184 4561,9184 4606,9139 4606,8842.02 U0.66@4563.75,8799.77 ; TFT_LCD.16@4290,10575 4339,10526 4339,10395.25 4334,10390.25 v1(4334,10382)
  Bottom Layer w10: v1(3640.57,9769.43) v1@3922.57,9769.43 ; v1(3891,10220) 4309,10220 4334,10245 v1(4334,10382)
FSMC_D11: TFT_LCD.17 U0.67 U1.32 | length 3113.9
  Top Layer w10: v1(3596.07,9737.93) U1.32@3712.91,9737.93 ; v1(3867,10186) 3898.5,10154.5 3898.5,9406.5 4139,9166 4534,9166 4588,9112 4588,8851.86 U0.67@4549.83,8813.69 ; v1(4390,10344) TFT_LCD.17@4390,10475
  Bottom Layer w10: v1(3596.07,9737.93) v1@3892.07,9737.93 ; v1@3875,10186 4354,10186 4390,10222 v1(4390,10344)
  other v1: 3898,9732
FSMC_D12: TFT_LCD.18 U0.68 U1.35 | length 3286.1
  Top Layer w10: v1(3597.56,9643.44) U1.35@3712.91,9643.44 ; v1(3840.5,10156.5) 3872.5,10124.5 3872.5,9642.5 v1(3873,9642) 3873,9392 4117,9148 4507,9148 4570,9085 4570,8861.7 U0.68@4535.91,8827.61 ; TFT_LCD.18@4390,10575 4390,10572 4442,10520 v1(4442,10386)
  Bottom Layer w10: v1(3597.56,9643.44) v1@3871.56,9643.44 ; v1(3840.5,10156.5) 4410.5,10156.5 4442,10188 v1(4442,10386)
FSMC_D13: TFT_LCD.19 U0.77 U1.36 | length 2875.2
  Top Layer w10: v1(3637.05,9611.95) U1.36@3712.91,9611.95 ; v1(3814.5,10126.5) 3847,10094 v1(3847,9611) 3847,9225 3904,9168 4052,9168 4240,8980 4240,8872.97 U0.77@4285.36,8827.61 ; v1(4490,10349) TFT_LCD.19@4490,10475
  Bottom Layer w10: v1(3637.05,9611.95) v1@3846.05,9611.95 ; v1@3815,10128 4469,10128 4490,10149 v1(4490,10349)
FSMC_D14: TFT_LCD.20 U0.78 U1.37 | length 3124.8
  Top Layer w10: v1(3599.45,9580.45) U1.37@3712.91,9580.45 ; v1(3798,10089) 3820,10067 3820,9215 3895,9140 4054.54,9140 4222,8972.54 4222,8863.13 U0.78@4271.44,8813.69 ; TFT_LCD.20@4490,10575 4540,10525 4540,10389 v1(4537,10386)
  Bottom Layer w10: v1(3599.45,9580.45) v1@3820,9580.45 ; v1(3798,10089) 4501,10089 4537,10125 v1(4537,10386)
  other v1: 3820,9581
FSMC_D15: TFT_LCD.21 U0.79 U1.38 | length 2880
  Top Layer w10: U1.38@3712.91,9548.95 3746.95,9548.95 3768,9570 ; v1(3741,10064) 3768,10037 3768,9591.05 ; 3767.95,9591.05 3767.95,9449.05 3802,9415 3802,9198 3890,9110 4059.09,9110 4204,8965.09 4204,8853.29 U0.79@4257.52,8799.77 ; v1(4590,10348) TFT_LCD.21@4590,10475
  Bottom Layer w10: v1@3741,10068 3748,10061 4544,10061 4590,10107 v1(4590,10348)
FSMC_NBL0: U0.141 U1.39 | length 2486.5
  Top Layer w10: v1(3594.46,9517.46) U1.39@3712.91,9517.46 ; v1(4201,8417) 4201,8376 4249,8328 4249,8181 4427,8003 4427,7939.21 U0.141@4299.28,7811.49
  Bottom Layer w10: v1(3594.46,9517.46) 3871.54,9517.46 3894,9495 3894,8900.91 3932.91,8862 4107,8862 4187,8782 4187,8431 v1(4201,8417)
FSMC_NBL1: U0.142 U1.40 | length 2421.6
  Top Layer w10: v1(3641.04,9485.96) U1.40@3712.91,9485.96 ; v1(4234,8387) 4255,8387 4267,8375 4267,8193 4457,8003 4457,7941.37 U0.142@4313.2,7797.57
  Bottom Layer w10: v1(3641.04,9485.96) 3844.04,9485.96 3876,9454 3876,8893.46 3925.46,8844 4098.46,8844 4167,8775.46 4167,8411 4191,8387 v1@4240,8387
FSMC_NE3: R2.2 U0.125 U1.6 | length 2236.3
  Top Layer w10: U0.125@4076.57,8034.2 4112,8069.63 4112,8284 v1(4128.5,8300.5) ; U1.6@4185.35,9517.46 R2.2@4380.98,9517.46 ; R2.2@4382.94,9515.5 4525,9515.5 4541,9499.5 v1(4541,9417)
  Bottom Layer w10: v1(4128.5,8300.5) 4505.5,8300.5 4538.5,8333.5 v1@4538.5,9415.5
FSMC_NE4: TFT_LCD.1 U0.127 | length 3169.6
  Top Layer w10: U0.127@4104.41,8006.36 4154,8055.95 v1(4154,8256)
  Bottom Layer w10: TFT_LCD.1@3590,10475 3590,10220 3566,10196 3487,10196 3465,10174 3465,8758 3535,8688 3940,8688 4030,8598 4030,8278 4052,8256 v1(4154,8256)
FSMC_NOE: TFT_LCD.4 U0.118 U1.41 | length 5587.5
  Top Layer w10: v1(3599.46,9454.46) U1.41@3712.91,9454.46 ; U0.118@3979.14,8131.64 4061.25,8213.75 4061.25,8307.25 v1(4143,8389)
  Bottom Layer w10: v1(3599.46,9454.46) 3832.54,9454.46 3858,9429 3858,8886 3918,8826 4091,8826 4142.5,8774.5 4142.5,8341.5 4164,8320 4388,8320 4456,8388 4456,9839 4384,9911 3583,9911 3537,9957 3537,10120 3567,10150 3705,10150 3740,10185 3740,10525 TFT_LCD.4@3690,10575
FSMC_NWE: TFT_LCD.3 U0.119 U1.17 | length 3790.3
  Top Layer w10: U0.119@3993.06,8117.72 4082.34,8207 4082.34,8302.88 4131.46,8352 v1(4185,8352) ; U1.17@4185.35,9863.91 v1(4280,9863.91)
  Bottom Layer w10: TFT_LCD.3@3690,10475 3690,10205 3654.5,10169.5 3547.5,10169.5 3500,10122 3500,9923 3559.09,9863.91 v1(4280,9863.91) 4386.09,9863.91 4433,9817 4433,8408 4377,8352 v1(4185,8352)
